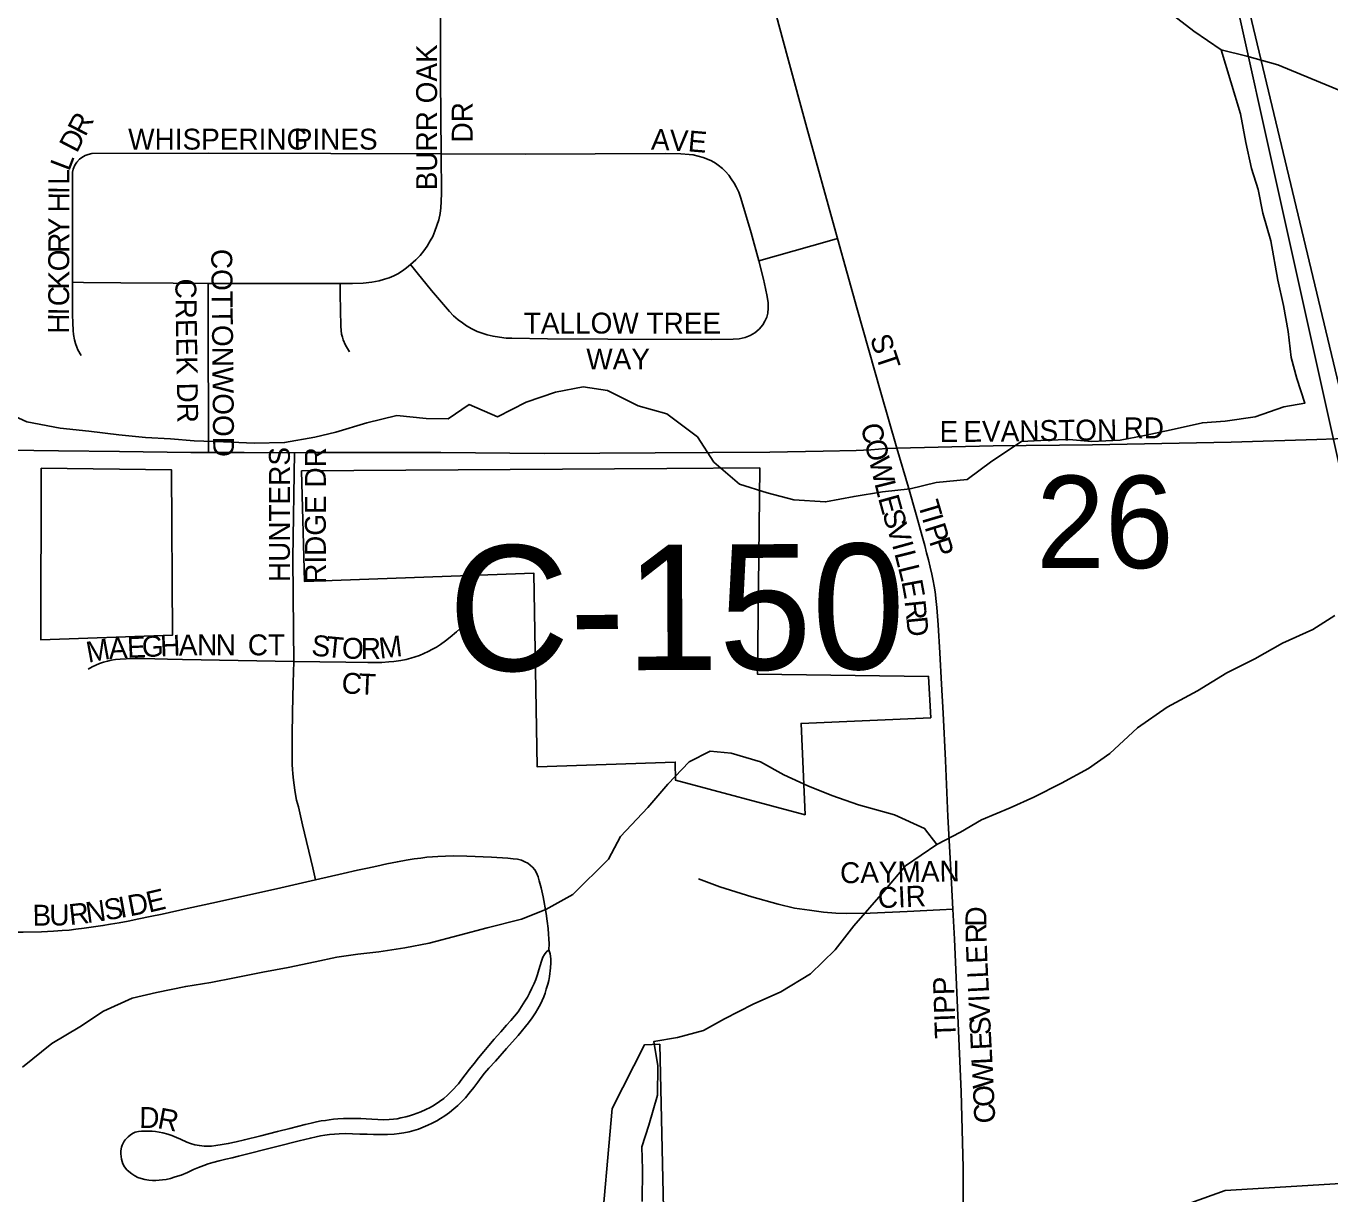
# Model space of a CAD drawing. Extents: x 0 to 680, y 0 to 440.
# Drawn here: x 507.7 to 518.1, y 209.11 to 218.44 of the extents above; entities that cross this region are included whole.
import ezdxf

# ---------------------------------------------------------------- set-up
doc = ezdxf.new("R2010")
doc.units = 0
for name, color, linetype in [('GM_X_City_Street', 7, 'Continuous'), ('GM_X_City_Street_Text', 7, 'Continuous'), ('GM_X_Corporation', 7, 'Continuous'), ('GM_X_County_Road', 7, 'Continuous'), ('GM_X_County_Road_Text', 7, 'Continuous'), ('GM_X_Minor_River', 7, 'Continuous'), ('GM_X_Rail_Line', 7, 'Continuous'), ('GM_X_Section_Text', 7, 'Continuous')]:
    doc.layers.add(name, color=color, linetype=linetype)

msp = doc.modelspace()

# ---------------------------------------------------------------- linework, layer by layer
at = {"layer": 'GM_X_City_Street'}
for points in [[(514.174, 216.74), (514.161, 216.786), (513.93, 217.622), (513.776, 218.189), (513.654, 218.644), (513.484, 219.31)], [(511.01, 217.415), (511.004, 218.013), (511.004, 218.484), (511.004, 218.595)], [(508.123, 217.372), (508.143, 217.387), (508.168, 217.401), (508.193, 217.411), (508.223, 217.417), (509.157, 217.421), (510.129, 217.417), (511.01, 217.415)], [(508.069, 216.389), (508.069, 216.714), (508.069, 217.27), (508.074, 217.293), (508.086, 217.325), (508.101, 217.349), (508.123, 217.372)], [(510.767, 216.532), (510.808, 216.568), (510.842, 216.604), (510.871, 216.64), (510.9, 216.679), (510.924, 216.72), (510.943, 216.755), (510.961, 216.797), (510.977, 216.842), (510.991, 216.889), (511.002, 216.94), (511.008, 216.984), (511.011, 217.034), (511.013, 217.102), (511.01, 217.415)], [(511.01, 217.415), (511.682, 217.413), (512.799, 217.418), (512.924, 217.416), (512.99, 217.41), (513.023, 217.406), (513.063, 217.397), (513.102, 217.385), (513.137, 217.372), (513.168, 217.359), (513.2, 217.34), (513.223, 217.324), (513.256, 217.299), (513.281, 217.273), (513.307, 217.244), (513.326, 217.216), (513.349, 217.182), (513.366, 217.151), (513.386, 217.108), (513.403, 217.062), (513.484, 216.784), (513.547, 216.56)], [(513.547, 216.56), (514.11, 216.721), (514.174, 216.74)], [(514.647, 215.065), (514.521, 215.51), (514.328, 216.184), (514.174, 216.74)], [(510.205, 216.379), (510.304, 216.379), (510.388, 216.382), (510.457, 216.39), (510.515, 216.401), (510.557, 216.413), (510.596, 216.426), (510.632, 216.441), (510.664, 216.458), (510.703, 216.482), (510.735, 216.504), (510.767, 216.532)], [(510.767, 216.532), (510.82, 216.466), (510.934, 216.325), (511.076, 216.156), (511.11, 216.122), (511.147, 216.09), (511.18, 216.065), (511.214, 216.042), (511.256, 216.018), (511.299, 215.997), (511.338, 215.983), (511.378, 215.97), (511.425, 215.958), (511.477, 215.95), (511.53, 215.944), (511.574, 215.942), (511.859, 215.939), (512.34, 215.936), (513.171, 215.932), (513.342, 215.935), (513.39, 215.938), (513.436, 215.949), (513.478, 215.965), (513.514, 215.986), (513.55, 216.016), (513.577, 216.049), (513.594, 216.078), (513.609, 216.11), (513.617, 216.142), (513.622, 216.183), (513.62, 216.226), (513.614, 216.275), (513.6, 216.339), (513.584, 216.413), (513.547, 216.56)], [(508.069, 216.389), (508.155, 216.388), (508.453, 216.386), (508.87, 216.382), (509.151, 216.38)], [(508.137, 215.804), (508.111, 215.851), (508.102, 215.872), (508.091, 215.9), (508.084, 215.93), (508.077, 215.971), (508.074, 216.003), (508.071, 216.066), (508.069, 216.129), (508.069, 216.389)], [(509.151, 216.38), (509.345, 216.38), (509.665, 216.38), (509.914, 216.38), (510.205, 216.379)], [(509.154, 215.031), (509.154, 215.079), (509.153, 215.379), (509.152, 215.796), (509.151, 216.286), (509.151, 216.38)], [(510.278, 215.834), (510.248, 215.887), (510.229, 215.929), (510.222, 215.952), (510.216, 215.976), (510.213, 216.005), (510.21, 216.038), (510.205, 216.295), (510.205, 216.379)], [(514.647, 215.065), (515.417, 215.082), (516.211, 215.09), (517.316, 215.112), (518.001, 215.135), (518.305, 215.144)], [(507.511, 215.049), (507.76, 215.046), (507.957, 215.044)], [(509.012, 215.031), (509.154, 215.031)], [(509.154, 215.031), (509.437, 215.03), (509.84, 215.027)], [(509.834, 213.362), (509.831, 213.608), (509.827, 214.185), (509.84, 215.027)], [(509.84, 215.027), (509.96, 215.029), (510.076, 215.029)], [(513.633, 215.033), (514.059, 215.04), (514.324, 215.047), (514.44, 215.052), (514.502, 215.057), (514.562, 215.061), (514.647, 215.065)], [(514.99, 213.43), (514.977, 213.654), (514.973, 213.724), (514.967, 213.792), (514.963, 213.84), (514.954, 213.918), (514.947, 213.963), (514.938, 214.006), (514.927, 214.058), (514.914, 214.115), (514.9, 214.172), (514.886, 214.228), (514.872, 214.286), (514.85, 214.362), (514.829, 214.438), (514.802, 214.536), (514.74, 214.751), (514.647, 215.065)], [(509.834, 213.362), (510.249, 213.355), (510.425, 213.353), (510.494, 213.352), (510.538, 213.354), (510.592, 213.358), (510.634, 213.362), (510.688, 213.369), (510.731, 213.378), (510.769, 213.388), (510.803, 213.398), (510.837, 213.41), (510.873, 213.425), (510.908, 213.44), (510.941, 213.458), (510.972, 213.475), (511.005, 213.497), (511.044, 213.526), (511.082, 213.556), (511.132, 213.598), (511.245, 213.698)], [(508.194, 213.3), (508.226, 213.317), (508.254, 213.332), (508.284, 213.345), (508.315, 213.355), (508.346, 213.364), (508.377, 213.371), (508.411, 213.376), (508.449, 213.38), (508.497, 213.383), (508.567, 213.384), (508.641, 213.384), (508.726, 213.383), (508.826, 213.38), (508.946, 213.377), (509.834, 213.362)], [(510.007, 211.617), (509.985, 211.712), (509.904, 212.056), (509.871, 212.201), (509.857, 212.253), (509.847, 212.298), (509.842, 212.333), (509.836, 212.374), (509.831, 212.413), (509.826, 212.464), (509.823, 212.501), (509.821, 212.536), (509.82, 212.591), (509.821, 212.769), (509.823, 212.953), (509.828, 213.191), (509.834, 213.362)], [(515.096, 211.382), (515.078, 211.693), (515.054, 212.122), (515.037, 212.569), (515.018, 212.949)], [(510.007, 211.617), (510.228, 211.667), (510.343, 211.693), (510.422, 211.71), (510.496, 211.726), (510.577, 211.744), (510.661, 211.761), (510.731, 211.774), (510.796, 211.784), (510.847, 211.791), (510.896, 211.797), (510.942, 211.802), (510.984, 211.804), (511.044, 211.807), (511.109, 211.809), (511.215, 211.807), (511.413, 211.799), (511.544, 211.79), (511.586, 211.786), (511.619, 211.781), (511.652, 211.773), (511.678, 211.762), (511.702, 211.749), (511.721, 211.734), (511.739, 211.718), (511.757, 211.696), (511.771, 211.673), (511.784, 211.641), (511.794, 211.609), (511.809, 211.552), (511.825, 211.48), (511.848, 211.347), (511.857, 211.286), (511.864, 211.228), (511.868, 211.184), (511.871, 211.145), (511.872, 211.106), (511.871, 211.058)], [(507.485, 211.199), (507.674, 211.199), (507.82, 211.203), (507.915, 211.208), (507.986, 211.212), (508.042, 211.216), (508.094, 211.222), (508.161, 211.231), (508.235, 211.241), (508.31, 211.252), (508.372, 211.263), (508.44, 211.274), (508.511, 211.287), (508.597, 211.305), (508.687, 211.323), (508.784, 211.344), (508.982, 211.387), (509.217, 211.439), (509.731, 211.554), (510.007, 211.617)], [(513.065, 211.625), (513.234, 211.562), (513.49, 211.481), (513.701, 211.423), (513.832, 211.392), (513.951, 211.374), (514.063, 211.36), (514.16, 211.35), (514.249, 211.348), (514.434, 211.352), (514.73, 211.365), (514.99, 211.377), (515.096, 211.382)], [(515.178, 209.319), (515.162, 209.925), (515.109, 211.142), (515.096, 211.382)], [(511.871, 211.058), (511.849, 211.039), (511.835, 211.022), (511.823, 210.999), (511.812, 210.968), (511.8, 210.932), (511.791, 210.899), (511.78, 210.86), (511.765, 210.821), (511.752, 210.79), (511.735, 210.753), (511.715, 210.712), (511.699, 210.68), (511.678, 210.647), (511.652, 210.605), (511.625, 210.564), (511.597, 210.528), (511.568, 210.493), (511.533, 210.456), (511.486, 210.403), (511.434, 210.345), (511.39, 210.295), (511.351, 210.247), (511.309, 210.196), (511.273, 210.15), (511.238, 210.105), (511.203, 210.06), (511.176, 210.024), (511.148, 209.988), (511.096, 209.931), (511.06, 209.896), (511.031, 209.872), (510.996, 209.846), (510.955, 209.818), (510.922, 209.799), (510.887, 209.782), (510.848, 209.765), (510.818, 209.753), (510.79, 209.743), (510.757, 209.733), (510.728, 209.724), (510.689, 209.715), (510.66, 209.709), (510.629, 209.705), (510.595, 209.702), (510.554, 209.701), (510.506, 209.702), (510.456, 209.705), (510.411, 209.708), (510.37, 209.711), (510.325, 209.712), (510.276, 209.712), (510.231, 209.711), (510.186, 209.708), (510.151, 209.705), (510.117, 209.701), (510.088, 209.696), (510.054, 209.691), (510.015, 209.683), (509.972, 209.673), (509.924, 209.662), (509.802, 209.631), (509.704, 209.607), (509.572, 209.573), (509.44, 209.541), (509.375, 209.525), (509.311, 209.511), (509.262, 209.502), (509.211, 209.494), (509.176, 209.491), (509.153, 209.491), (509.118, 209.491), (509.081, 209.494), (509.045, 209.501), (509.01, 209.511), (508.981, 209.523), (508.93, 209.546), (508.898, 209.56), (508.86, 209.576), (508.829, 209.586), (508.79, 209.596), (508.759, 209.602), (508.729, 209.607), (508.703, 209.609), (508.675, 209.611), (508.645, 209.611), (508.619, 209.609), (508.594, 209.607), (508.569, 209.601), (508.548, 209.591), (508.529, 209.579), (508.511, 209.565), (508.498, 209.552), (508.489, 209.541), (508.481, 209.53), (508.472, 209.513), (508.465, 209.498), (508.459, 209.482), (508.453, 209.452)], [(511.871, 211.058), (511.88, 211.025), (511.886, 210.986), (511.886, 210.955), (511.884, 210.915), (511.875, 210.844), (511.87, 210.813), (511.862, 210.784), (511.85, 210.744), (511.841, 210.713), (511.829, 210.682), (511.817, 210.654), (511.803, 210.624), (511.783, 210.587), (511.764, 210.556), (511.738, 210.516), (511.709, 210.475), (511.626, 210.373), (511.533, 210.269), (511.444, 210.17), (511.392, 210.112), (511.356, 210.072), (511.331, 210.038), (511.302, 210.001), (511.27, 209.959), (511.235, 209.912), (511.206, 209.877), (511.174, 209.844), (511.144, 209.815), (511.113, 209.789), (511.077, 209.76), (511.039, 209.733), (511.006, 209.711), (510.976, 209.693), (510.938, 209.673), (510.905, 209.657), (510.867, 209.641), (510.829, 209.627), (510.792, 209.615), (510.755, 209.605), (510.712, 209.596), (510.674, 209.591), (510.635, 209.586), (510.583, 209.582), (510.532, 209.582), (510.47, 209.583), (510.42, 209.586), (510.362, 209.587), (510.303, 209.588), (510.245, 209.59), (510.196, 209.588), (510.158, 209.586), (510.119, 209.583), (510.082, 209.578), (510.048, 209.572), (510.013, 209.565), (509.967, 209.554), (509.878, 209.532), (509.699, 209.487), (509.393, 209.41), (509.342, 209.397), (509.293, 209.386), (509.239, 209.373), (509.189, 209.36), (509.151, 209.348), (509.116, 209.336), (509.074, 209.32), (509.034, 209.303), (508.986, 209.281), (508.934, 209.259), (508.886, 209.244), (508.851, 209.233), (508.815, 209.225), (508.787, 209.221), (508.76, 209.218), (508.733, 209.215), (508.705, 209.216), (508.676, 209.219), (508.644, 209.225), (508.616, 209.231), (508.59, 209.241), (508.566, 209.253), (508.542, 209.269), (508.517, 209.288), (508.502, 209.301), (508.482, 209.326), (508.47, 209.348), (508.463, 209.367), (508.459, 209.387), (508.456, 209.407), (508.454, 209.429), (508.453, 209.452)]]:
    msp.add_lwpolyline(points, dxfattribs=at)
at = {"layer": 'GM_X_Corporation'}
for points in [[(518.507, 219.576), (517.23, 219.532), (518.324, 214.944)], [(512.788, 208.873), (512.756, 210.304), (512.633, 210.298), (512.375, 209.792), (512.277, 208.678)], [(519.51, 209.271), (517.269, 209.135), (515.068, 208.344)]]:
    msp.add_lwpolyline(points, dxfattribs=at)
for points in [[(507.818, 214.905), (507.815, 213.533), (508.865, 213.57), (508.857, 214.892)], [(509.896, 214.884), (509.919, 214.001), (511.751, 214.065), (511.778, 212.519), (512.879, 212.558), (512.881, 212.414), (513.915, 212.137), (513.884, 212.866), (514.918, 212.911), (514.901, 213.241), (513.536, 213.259), (513.553, 214.907), (512.813, 214.903)]]:
    msp.add_lwpolyline(points, close=True, dxfattribs=at)
at = {"layer": 'GM_X_County_Road'}
for points in [[(507.957, 215.044), (508.444, 215.039), (509.012, 215.031)], [(510.076, 215.029), (511.009, 215.029), (511.836, 215.022), (512.719, 215.027), (513.633, 215.033)], [(515.018, 212.949), (515.005, 213.181), (514.99, 213.43)], [(515.107, 206.166), (515.133, 206.911), (515.156, 207.875), (515.176, 208.688), (515.178, 209.315), (515.178, 209.319)]]:
    msp.add_lwpolyline(points, dxfattribs=at)
at = {"layer": 'GM_X_Minor_River'}
for points in [[(518.275, 217.884), (517.876, 218.05), (517.69, 218.126), (517.443, 218.196), (517.237, 218.245), (517.018, 218.395), (516.786, 218.572)], [(507.444, 215.391), (507.703, 215.274), (507.97, 215.224), (508.197, 215.201), (508.437, 215.172), (508.651, 215.149), (508.851, 215.14), (509.038, 215.124), (509.272, 215.115), (509.519, 215.105), (509.76, 215.109), (510.001, 215.153), (510.169, 215.191), (510.417, 215.268), (510.658, 215.325), (510.892, 215.302), (511.066, 215.3), (511.234, 215.412), (511.46, 215.316), (511.689, 215.433), (511.924, 215.511), (512.145, 215.555), (512.338, 215.526), (512.584, 215.402), (512.811, 215.339), (513.056, 215.156), (513.187, 214.953), (513.392, 214.777), (513.612, 214.707), (513.825, 214.651), (514.079, 214.635), (514.306, 214.679), (514.534, 214.716), (514.755, 214.74), (514.963, 214.791), (515.21, 214.815), (515.406, 214.96), (515.642, 215.118), (515.849, 215.129), (516.023, 215.133), (516.203, 215.118), (516.43, 215.128), (516.625, 215.166), (516.839, 215.211), (517.087, 215.268), (517.268, 215.279), (517.509, 215.316), (517.737, 215.394), (517.905, 215.425), (517.84, 215.62), (517.795, 215.788), (517.771, 215.996), (517.734, 216.204), (517.689, 216.405), (517.633, 216.721), (517.569, 216.942), (517.531, 217.13), (517.479, 217.298), (517.435, 217.506), (517.391, 217.734), (517.237, 218.245)], [(518.145, 213.729), (517.969, 213.617), (517.727, 213.506), (517.505, 213.382), (517.283, 213.27), (517.048, 213.126), (516.806, 212.995), (516.57, 212.83), (516.347, 212.626), (516.178, 212.507), (515.963, 212.389), (515.741, 212.278), (515.553, 212.193), (515.324, 212.096), (515.156, 211.997), (514.968, 211.899), (514.718, 211.728), (514.542, 211.522), (514.305, 211.251), (514.155, 211.058), (513.959, 210.867), (513.723, 210.722), (513.502, 210.624), (513.273, 210.507), (513.105, 210.415), (512.897, 210.357), (512.709, 210.326), (512.74, 210.132), (512.738, 209.897), (512.668, 209.657), (512.612, 209.484), (512.617, 209.303), (512.614, 209.048)], [(514.968, 211.899), (514.869, 212.027), (514.63, 212.137), (514.343, 212.215), (514.13, 212.291), (513.937, 212.367), (513.745, 212.456), (513.559, 212.559), (513.326, 212.629), (513.159, 212.644), (512.991, 212.559), (512.821, 212.38), (512.659, 212.195), (512.442, 211.963), (512.346, 211.783), (512.062, 211.499), (511.847, 211.381), (511.652, 211.303), (511.377, 211.233), (511.156, 211.175), (510.914, 211.111), (510.72, 211.073), (510.513, 211.042), (510.345, 211.024), (510.178, 211), (510.004, 210.961), (509.789, 210.917), (509.588, 210.88), (509.361, 210.835), (509.173, 210.798), (508.972, 210.766), (508.737, 210.716), (508.543, 210.671), (508.315, 210.567), (508.126, 210.442), (507.904, 210.311), (507.668, 210.12)]]:
    msp.add_lwpolyline(points, dxfattribs=at)
at = {"layer": 'GM_X_Rail_Line'}
msp.add_lwpolyline([(517.428, 188.131), (518.134, 191.453), (519.378, 197.467), (519.854, 199.812), (519.978, 200.427), (520.069, 201.042), (520.154, 201.733), (520.212, 202.486), (520.245, 203.162), (520.235, 203.844), (520.212, 204.483), (520.174, 205.145), (520.107, 205.717), (520.04, 206.241), (519.83, 207.485), (519.668, 208.186), (519.218, 210.245), (515.811, 225.596)], dxfattribs=at)

# ---------------------------------------------------------------- texts
at = {"layer": 'GM_X_City_Street_Text'}
for s, height, rotation, p in [('BURR OAK', 0.1669, 90, (510.978, 217.124)), ('R', 0.167, 62.716, (508.17, 217.546)), ('DR', 0.1669, 90, (511.262, 217.506)), ('D', 0.167, 62.5031, (508.102, 217.415)), ('WHISPERING', 0.1669, 0, (508.512, 217.449)), ('PINES', 0.1669, 0, (509.834, 217.449)), ('A', 0.167, 357.4421, (512.684, 217.449)), ('V', 0.167, 357.4427, (512.831, 217.442)), ('E', 0.167, 355.0752, (512.976, 217.436)), ('L', 0.167, 69.1018, (508.041, 217.27)), ('L', 0.167, 89.8634, (508.043, 217.168)), ('I', 0.167, 89.8565, (508.043, 217.094)), ('H', 0.167, 89.847, (508.043, 216.947)), ('Y', 0.167, 89.8633, (508.042, 216.757)), ('R', 0.167, 89.8516, (508.042, 216.624)), ('O', 0.167, 89.847, (508.041, 216.477)), ('COTTONWOOD', 0.1669, 270.5743, (509.175, 216.655)), ('K', 0.167, 89.8633, (508.041, 216.331)), ('CREEK DR', 0.1669, 270.858, (508.888, 216.418)), ('C', 0.167, 89.8543, (508.041, 216.198)), ('H', 0.167, 89.847, (508.04, 215.978)), ('I', 0.167, 89.8655, (508.041, 216.125)), ('TALLOW TREE', 0.16689, 0, (511.67, 215.98)), ('ST', 0.1669, 288.4371, (514.431, 215.944)), ('WAY', 0.1669, 0, (512.169, 215.693)), ('C', 0.167, 283.3059, (514.358, 215.244)), ('E', 0.167, 0, (514.989, 215.114)), ('EVANSTON', 0.1669, 0.6737, (515.18, 215.114)), ('RD', 0.1669, 0, (516.458, 215.143)), ('O', 0.167, 283.327, (514.389, 215.115)), ('HUNTERS', 0.1669, 90, (509.803, 213.995)), ('RIDGE DR', 0.1669, 90, (510.09, 213.981)), ('W', 0.167, 283.4871, (514.423, 214.972)), ('L', 0.167, 283.9403, (514.468, 214.784)), ('E', 0.167, 285.4281, (514.497, 214.666)), ('T', 0.167, 286.4258, (514.814, 214.621)), ('S', 0.167, 286.7439, (514.53, 214.549)), ('I', 0.167, 286.4518, (514.847, 214.508)), ('V', 0.167, 287.5228, (514.564, 214.434)), ('P', 0.167, 287.3031, (514.868, 214.435)), ('I', 0.167, 285.5791, (514.608, 214.295)), ('P', 0.167, 288.344, (514.904, 214.32)), ('L', 0.167, 284.1025, (514.627, 214.225)), ('L', 0.167, 283.907, (514.656, 214.112)), ('E', 0.167, 280.4124, (514.684, 214)), ('R', 0.167, 275.8628, (514.709, 213.844)), ('D', 0.167, 275.5388, (514.723, 213.713)), ('G', 0.167, 2.6343, (508.625, 213.395)), ('H', 0.167, 2.4924, (508.771, 213.401)), ('A', 0.167, 0.8306, (508.917, 213.408)), ('N', 0.167, 0.0328, (509.063, 213.41)), ('N', 0.167, 0, (509.21, 213.41)), ('CT', 0.1669, 0, (509.467, 213.41)), ('S', 0.167, 354.1018, (509.97, 213.41)), ('M', 0.167, 6.8731, (510.523, 213.383)), ('M', 0.167, 10.4775, (508.194, 213.35)), ('A', 0.167, 3.2041, (508.361, 213.381)), ('E', 0.167, 2.6373, (508.507, 213.389)), ('T', 0.167, 354.4087, (510.087, 213.398)), ('O', 0.167, 358.3433, (510.217, 213.385)), ('R', 0.167, 0.2077, (510.369, 213.381)), ('C', 0.167, 355.7466, (510.211, 213.109)), ('T', 0.167, 357.6181, (510.349, 213.099)), ('CAYMAN', 0.1669, 0.938, (514.196, 211.589)), ('D', 0.167, 10.8271, (508.526, 211.325)), ('E', 0.167, 13.181, (508.678, 211.354)), ('CIR', 0.1669, 2.4883, (514.499, 211.39)), ('B', 0.167, 0.1336, (507.749, 211.251)), ('U', 0.167, 1.0462, (507.884, 211.251)), ('R', 0.167, 6.4481, (508.048, 211.255)), ('N', 0.167, 7.9986, (508.184, 211.271)), ('S', 0.167, 9.4621, (508.334, 211.292)), ('I', 0.167, 10.2595, (508.452, 211.312)), ('D', 0.167, 90.2841, (515.363, 211.244)), ('R', 0.167, 91.4087, (515.366, 211.112)), ('E', 0.167, 92.2409, (515.372, 210.951)), ('L', 0.167, 92.7328, (515.378, 210.834)), ('TIPP', 0.1669, 91.9738, (515.119, 210.352)), ('L', 0.167, 92.8153, (515.384, 210.717)), ('I', 0.167, 92.8428, (515.387, 210.644)), ('V', 0.167, 92.8397, (515.395, 210.497)), ('S', 0.167, 92.8153, (515.4, 210.38)), ('E', 0.167, 92.8351, (515.406, 210.262)), ('L', 0.167, 92.8153, (515.412, 210.145)), ('W', 0.167, 92.8364, (515.422, 209.954)), ('O', 0.167, 92.8204, (515.429, 209.808)), ('C', 0.167, 92.8424, (515.435, 209.676)), ('D', 0.167, 359.4535, (508.6, 209.636)), ('R', 0.167, 349.2163, (508.739, 209.635))]:
    msp.add_text(s, height=height, rotation=rotation, dxfattribs=at).set_placement(p)
at = {"layer": 'GM_X_County_Road_Text'}
msp.add_text('C-150', height=1.0014, rotation=0.2742, dxfattribs=at).set_placement((511.069, 213.284))
at = {"layer": 'GM_X_Section_Text'}
msp.add_text('26', height=0.7377, rotation=0, dxfattribs=at).set_placement((515.76, 214.107))

doc.saveas('drawing.dxf')
